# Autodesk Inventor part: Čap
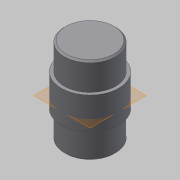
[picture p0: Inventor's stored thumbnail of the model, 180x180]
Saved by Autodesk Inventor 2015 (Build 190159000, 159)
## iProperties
Created: 2012-09
Part Number: Čap
Document SubType Name: Modeling
Designer: Michman
Material: Všeobecné
Density: 1 g/cm^3
Appearance: Výchozí
Author: Michman
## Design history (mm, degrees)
sketch "Náčrt1"
  geometry: C1 r 9 at (0, 0)
  constraints: 1 centre point
  dimensions: "d0" = 18 diameter of C1
extrude "Vysunutí1" new body sketch "Náčrt1" distance "d1" = 15; taper "d2" = 0 deg
sketch "Náčrt2"
  geometry: C1 r 9 at (0, 0) reference; C2 r 8 at (0, 0)
  constraints: 1 centre point, 1 coincident
  dimensions: "d3" = 16 diameter of C2
extrude "Vysunutí2" join sketch "Náčrt2" distance "d4" = 8.5; taper "d5" = 0 deg
chamfer "Zkosení2" distance "d10" = 0.5; stored, may be unused: second distance "d11" = 2, angle "d12" = 45 deg
sketch "Náčrt3"
  geometry: C1 r 9 at (0, 0) reference; C2 r 8 at (0, 0)
  constraints: 1 centre point, 1 coincident
  dimensions: "d13" = 16 diameter of C2
extrude "Vysunutí3" join sketch "Náčrt3" distance "d14" = 8.5; taper "d15" = 0 deg
chamfer "Zkosení3" distance "d16" = 0.5; stored, may be unused: second distance "d17" = 2, angle "d18" = 45 deg
node "Pracovní rovina2"
node "Těleso1"
node "Objemová tělesa"
node "Povrchová tělesa"
